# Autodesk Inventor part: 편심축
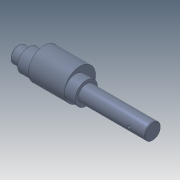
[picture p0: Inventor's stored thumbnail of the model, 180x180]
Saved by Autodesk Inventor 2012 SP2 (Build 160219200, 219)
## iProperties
Manager: 한국ATC센터
Company: 한국ATC센터
Created: 2014-07
Part Number: 편심축
Document SubType Name: Modeling
Designer: KYOUNG IL JANG
Density: 7.86 g/cm^3
Material: 강, 연강
Mass: 1544.74 g
Surface Area: 256.354 cm^2
Volume: 196.531 cm^3
Author: KYOUNG IL JANG
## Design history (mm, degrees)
sketch "스케치1"
  geometry: L1 (-105, 0)-(105, 0); L2 (-105, 0)-(-105, 12.5); L3 (-105, 12.5)-(-89, 12.5); L4 (-89, 12.5)-(-89, 17.5); L5 (-89, 17.5)-(-82, 17.5); L6 (-82, 17.5)-(-82, 12.5); L7 (-82, 12.5)-(-0.35, 12.5); L8 (-0.35, 12.5)-(-0.35, 11.95); L9 (-0.35, 11.95)-(1, 11.95); L10 (1, 11.95)-(1, 12.5); L11 (1, 12.5)-(105, 12.5); L12 (105, 12.5)-(105, 0); L13 (70, 12.5)-(70, 9.1); L14 (70, 9.1)-(95, 9.1); L15 (95, 9.1)-(95, 12.5); L16 (80, -12.5)-(82.5, -12.5); L17 (82.5, -12.5)-(80, -10); L18 (80, -10)-(80, -12.5); L19 (1, 12.5)-(-0.35, 12.5); 2 further points
  constraints: 38 end point, 8 parallel, 5 collinear, 5 perpendicular, 2 point on line, 1 coincident, 1 horizontal, 1 midpoint, 1 vertical
  dimensions: "d0" = 210 distance of L1.start L1.end; "d1" = 25 diameter of L3 L1; "d2" = 35 diameter of L5 L1; "d3" = 16 distance of L2.end L3.end; "d6" = 1.35 distance of L8.end L9.end; "d7" = 23.9 diameter of L9 L1; "d8" = 3.4 distance between parallel lines of L14 L11; "d9" = 10 distance between parallel lines of L15 L12; "d10" = 25 distance of L13.end L14.end; "d11" = 25 diameter of L16 L1 (= d1); "d12" = 25 distance from line of L12 L16.start; "d13" = 45 deg angle of L17 L18; "d14" = 5 diameter of L16.end L18; "d27" = 104 distance between parallel lines of L10 L12; "d35" = 7 distance of L4.end L5.end
revolve "회전1" stored, may be unused: angle "d15" = 90 deg
revolve "회전2" stored, may be unused: angle "d16" = 90 deg
extrude "돌출1" cut sketch "스케치1" stored distance "d17" = 8; taper "d18" = 0 deg
fillet "모깎기1" dims "d19" = 4
node "작업 평면1"
sketch "스케치2"
  geometry: C1 r 12.5 at (0, 0) reference; C2 r 17.5 at (0, 0); C3 r 24.5 at (0, 7); 1 further point
  constraints: 2 centre point, 1 coincident, 1 tangent, 1 vertical alignment
  dimensions: "d32" = 35 diameter of C2; "d33" = 49 diameter of C3 (derived); "d34" = 7 distance of C3.centre point (0, 0)
extrude "돌출2" join sketch "스케치2" distance "d22" = 56; taper "d23" = 0 deg
chamfer "모따기1" distance "d24" = 1; stored, may be unused: second distance "d25" = 2, angle "d26" = 45 deg
feature "면 이동1" dims "d31" = 83
node "솔리드1"
